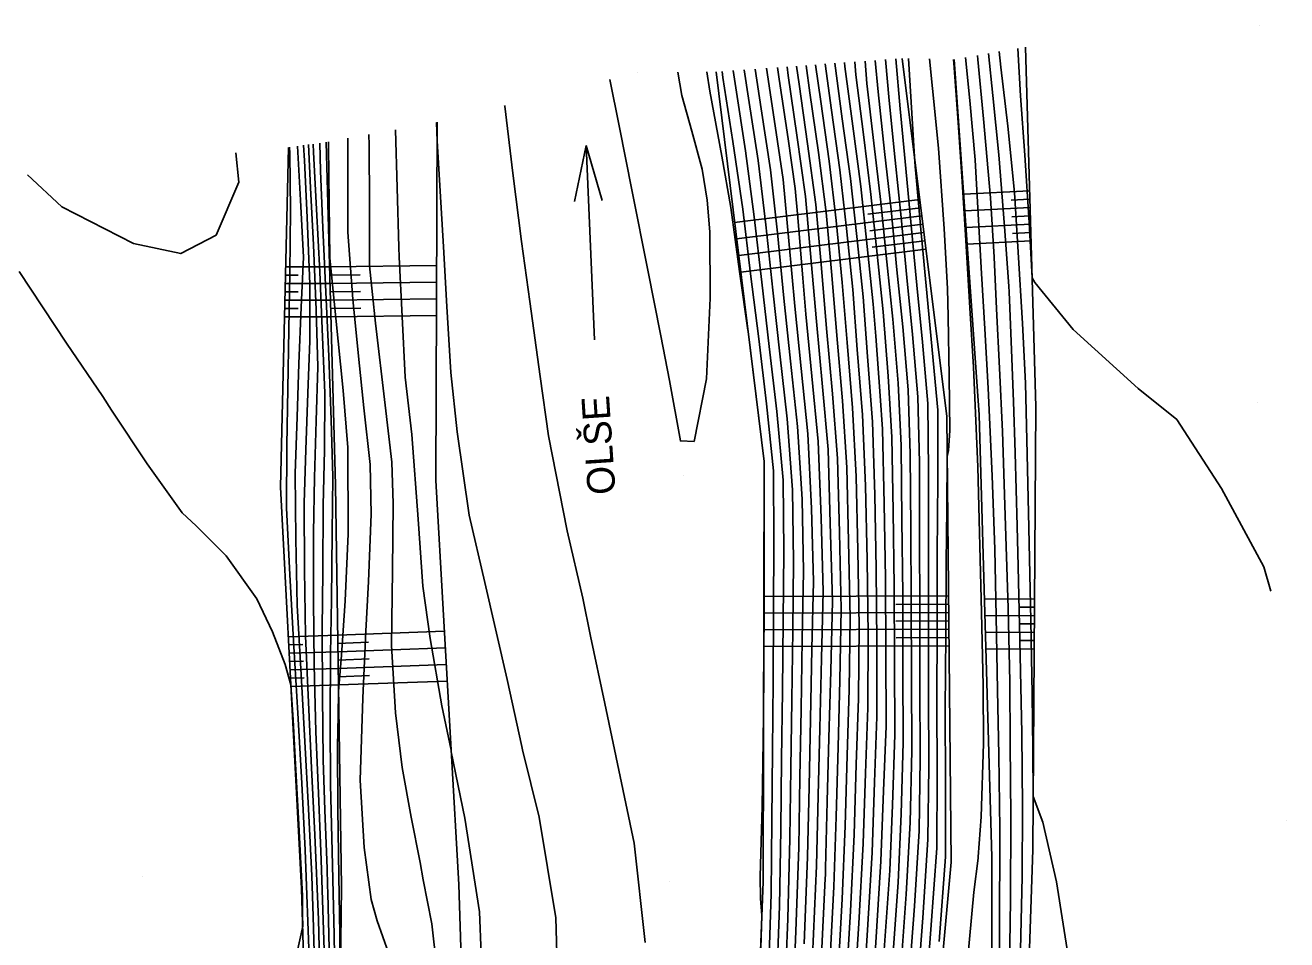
# Model space of a CAD drawing. Extents: x -448957 to -448612, y -1107690 to -1107245.
# Drawn here: x -448660.15 to -448614.67, y -1107277.56 to -1107244.62 of the extents above; entities that cross this region are included whole.
import ezdxf

# ---------------------------------------------------------------- set-up
doc = ezdxf.new("R2010")
doc.units = 0
for name, color, linetype in [('Default', 7, 'Continuous'), ('Vrstva 1', 7, 'Continuous'), ('Vrstva 14', 7, 'Continuous'), ('Vrstva 15', 7, 'Continuous'), ('Vrstva 16', 7, 'Continuous'), ('Vrstva 17', 7, 'Continuous'), ('Vrstva 45', 7, 'Continuous')]:
    doc.layers.add(name, color=color, linetype=linetype)

# ---------------------------------------------------------------- blocks, each defined once
blk = doc.blocks.new('POINT_DISPLAY')
at = {"layer": 'Default'}
blk.add_line((0, 0), (0, 0), dxfattribs=at)
blk = doc.blocks.new('TOK')
at = {"layer": 'Default'}
for p, q in [((-5, 50), (0, 70)), ((0, 0), (0, 70)), ((0, 70), (5, 50))]:
    blk.add_line(p, q, dxfattribs=at)

msp = doc.modelspace()

# ---------------------------------------------------------------- linework, layer by layer
at = {"layer": 'Vrstva 14'}
for p, q in [((-448623.72, -1107258.37), (-448624.094, -1107245.405)), ((-448626.923, -1107258.712), (-448628.535, -1107245.816)), ((-448625.755, -1107258.656), (-448626.659, -1107245.854)), ((-448633.514, -1107260.33), (-448635.246, -1107246.3)), ((-448645.345, -1107261.017), (-448645.297, -1107248.115)), ((-448650.94, -1107261.265), (-448650.655, -1107249.019)), ((-448648.961, -1107261.189), (-448649.302, -1107248.836)), ((-448626.769, -1107274.771), (-448626.923, -1107258.712)), ((-448625.299, -1107274.588), (-448625.755, -1107258.656)), ((-448623.821, -1107274.324), (-448623.72, -1107258.37)), ((-448633.55, -1107275.465), (-448633.514, -1107260.33)), ((-448644.514, -1107275.578), (-448645.345, -1107261.017)), ((-448650.184, -1107275.718), (-448650.94, -1107261.265)), ((-448648.744, -1107275.651), (-448648.961, -1107261.189)), ((-448625.345, -1107293.247), (-448625.299, -1107274.588)), ((-448624.486, -1107293.318), (-448623.821, -1107274.324)), ((-448628.426, -1107292.921), (-448626.769, -1107274.771)), ((-448643.962, -1107293.754), (-448644.514, -1107275.578)), ((-448634.19, -1107293.206), (-448633.55, -1107275.465)), ((-448649.646, -1107293.659), (-448650.184, -1107275.718)), ((-448648.982, -1107293.658), (-448648.744, -1107275.651))]:
    msp.add_line(p, q, dxfattribs=at)
at = {"layer": 'Vrstva 15'}
for p, q in [((-448623.944, -1107250.59), (-448626.316, -1107250.708)), ((-448627.9, -1107250.895), (-448634.576, -1107251.724)), ((-448623.936, -1107250.89), (-448624.613, -1107250.924)), ((-448627.826, -1107251.49), (-448634.503, -1107252.32)), ((-448627.863, -1107251.192), (-448629.77, -1107251.429)), ((-448623.927, -1107251.19), (-448626.274, -1107251.307)), ((-448623.918, -1107251.49), (-448624.589, -1107251.524)), ((-448627.789, -1107251.788), (-448629.696, -1107252.025)), ((-448623.91, -1107251.79), (-448626.232, -1107251.906)), ((-448627.751, -1107252.086), (-448634.429, -1107252.915)), ((-448627.714, -1107252.383), (-448629.622, -1107252.62)), ((-448623.893, -1107252.39), (-448626.189, -1107252.504)), ((-448623.901, -1107252.09), (-448624.565, -1107252.123)), ((-448627.677, -1107252.681), (-448634.356, -1107253.511)), ((-448650.755, -1107253.325), (-448649.178, -1107253.321)), ((-448649.178, -1107253.322), (-448645.316, -1107253.275)), ((-448650.762, -1107253.625), (-448650.303, -1107253.624)), ((-448649.17, -1107253.622), (-448648.072, -1107253.608)), ((-448650.776, -1107254.225), (-448650.308, -1107254.224)), ((-448650.769, -1107253.925), (-448649.162, -1107253.921)), ((-448649.162, -1107253.921), (-448645.318, -1107253.876)), ((-448649.153, -1107254.221), (-448648.061, -1107254.208)), ((-448650.783, -1107254.525), (-448649.145, -1107254.521)), ((-448649.145, -1107254.521), (-448645.321, -1107254.476)), ((-448650.797, -1107255.125), (-448649.129, -1107255.121)), ((-448650.79, -1107254.825), (-448650.313, -1107254.824)), ((-448649.137, -1107254.821), (-448648.049, -1107254.808)), ((-448649.129, -1107255.121), (-448645.323, -1107255.076)), ((-448626.861, -1107265.179), (-448633.526, -1107265.203)), ((-448626.858, -1107265.479), (-448628.762, -1107265.486)), ((-448623.764, -1107265.278), (-448625.565, -1107265.298)), ((-448623.766, -1107265.578), (-448624.28, -1107265.583)), ((-448626.855, -1107265.779), (-448633.527, -1107265.803)), ((-448623.768, -1107265.878), (-448625.548, -1107265.898)), ((-448648.88, -1107266.586), (-448645.035, -1107266.447)), ((-448626.849, -1107266.379), (-448633.528, -1107266.403)), ((-448626.852, -1107266.079), (-448628.759, -1107266.086)), ((-448623.771, -1107266.478), (-448625.531, -1107266.497)), ((-448623.769, -1107266.178), (-448624.278, -1107266.183)), ((-448650.659, -1107266.646), (-448648.88, -1107266.586)), ((-448650.643, -1107266.945), (-448650.141, -1107266.928)), ((-448648.876, -1107266.886), (-448647.77, -1107266.846)), ((-448626.847, -1107266.679), (-448628.755, -1107266.686)), ((-448623.773, -1107266.778), (-448624.276, -1107266.783)), ((-448650.627, -1107267.245), (-448648.871, -1107267.186)), ((-448648.871, -1107267.186), (-448645.001, -1107267.046)), ((-448626.844, -1107266.979), (-448633.53, -1107267.003)), ((-448623.775, -1107267.078), (-448625.513, -1107267.097)), ((-448650.612, -1107267.545), (-448650.116, -1107267.528)), ((-448650.596, -1107267.844), (-448648.862, -1107267.786)), ((-448648.867, -1107267.486), (-448647.754, -1107267.446)), ((-448648.862, -1107267.786), (-448644.967, -1107267.646)), ((-448650.58, -1107268.144), (-448650.091, -1107268.127)), ((-448648.858, -1107268.086), (-448647.737, -1107268.046)), ((-448648.853, -1107268.386), (-448644.933, -1107268.245)), ((-448650.565, -1107268.444), (-448648.853, -1107268.386))]:
    msp.add_line(p, q, dxfattribs=at)
at = {"layer": 'Vrstva 16'}
for points in [[(-448625.034, -1107245.57), (-448624.975, -1107246.128), (-448624.726, -1107248.256), (-448624.492, -1107250.651), (-448624.355, -1107252.799), (-448624.197, -1107255.366), (-448624.096, -1107257.514), (-448624.027, -1107260.071), (-448623.97, -1107262.72), (-448623.902, -1107266.064), (-448623.853, -1107268.714), (-448623.827, -1107270.707), (-448623.809, -1107272.4), (-448623.462, -1107273.321), (-448622.968, -1107275.478), (-448622.456, -1107278.756)], [(-448631.654, -1107246.041), (-448631.473, -1107247.37), (-448631.172, -1107249.517), (-448630.911, -1107251.655), (-448630.693, -1107253.887), (-448630.524, -1107256.046), (-448630.327, -1107258.407), (-448630.197, -1107260.88), (-448630.134, -1107263.547), (-448630.087, -1107266.27), (-448630.111, -1107268.878), (-448630.189, -1107271.246), (-448630.27, -1107273.776), (-448630.4, -1107276.535), (-448630.578, -1107279.549)], [(-448629.874, -1107245.913), (-448629.805, -1107246.717), (-448629.553, -1107248.868), (-448629.301, -1107250.993), (-448629.084, -1107253.146), (-448628.87, -1107255.214), (-448628.684, -1107257.512), (-448628.573, -1107259.76), (-448628.547, -1107262.436), (-448628.516, -1107265.124), (-448628.508, -1107267.805), (-448628.494, -1107270.456), (-448628.567, -1107273.023), (-448628.684, -1107275.497), (-448628.899, -1107278.516)], [(-448627.556, -1107245.836), (-448627.442, -1107246.899), (-448627.23, -1107249.047), (-448627.024, -1107251.959), (-448626.903, -1107254.106), (-448626.877, -1107255.121), (-448626.845, -1107257.262), (-448626.823, -1107259.214), (-448626.865, -1107259.937), (-448626.909, -1107260.153), (-448626.932, -1107262.019), (-448626.954, -1107263.985), (-448626.967, -1107266.578), (-448626.981, -1107269.265), (-448626.97, -1107271.909), (-448626.969, -1107274.577), (-448627.203, -1107277.623)], [(-448635.581, -1107246.303), (-448635.47, -1107246.998), (-448635.042, -1107249.34), (-448634.714, -1107251.183), (-448634.399, -1107253.491), (-448634.098, -1107255.602), (-448634.091, -1107255.654), (-448633.8, -1107257.991), (-448633.509, -1107260.335), (-448633.511, -1107262.858), (-448633.514, -1107265.387), (-448633.526, -1107267.587), (-448633.536, -1107269.774), (-448633.543, -1107270.068), (-448633.551, -1107270.392), (-448633.588, -1107272.762), (-448633.655, -1107275.283), (-448633.641, -1107276.077), (-448633.594, -1107276.689), (-448633.664, -1107279.033)], [(-448633.431, -1107246.169), (-448633.153, -1107248.002), (-448632.822, -1107250.173), (-448632.618, -1107252.385), (-448632.404, -1107254.742), (-448632.177, -1107256.989), (-448631.94, -1107259.339), (-448631.802, -1107262.03), (-448631.738, -1107264.663), (-448631.79, -1107267.087), (-448631.845, -1107269.614), (-448631.894, -1107272.044), (-448631.943, -1107274.571), (-448632.064, -1107277.71)], [(-448637.804, -1107277.666), (-448638.201, -1107274.086), (-448639.255, -1107269.048), (-448639.771, -1107266.623), (-448640.047, -1107265.257), (-448640.613, -1107262.833), (-448641.278, -1107259.412), (-448641.584, -1107257.268), (-448641.959, -1107254.568), (-448642.26, -1107252.415), (-448642.564, -1107249.955), (-448642.861, -1107247.54), (-448642.866, -1107247.512)], [(-448649.677, -1107279.715), (-448649.762, -1107276.72), (-448649.816, -1107275.256), (-448649.94, -1107272.847), (-448650.069, -1107270.417), (-448650.201, -1107268.008), (-448650.338, -1107265.528), (-448650.397, -1107263.118), (-448650.418, -1107260.77), (-448650.349, -1107258.729), (-448650.283, -1107256.819), (-448650.199, -1107254.777), (-448650.118, -1107252.977), (-448650.225, -1107250.927), (-448650.333, -1107248.975)], [(-448648.789, -1107279.043), (-448648.81, -1107277.349), (-448648.846, -1107275.273), (-448648.872, -1107272.862), (-448648.887, -1107270.593), (-448648.869, -1107269.486), (-448648.85, -1107268.62), (-448648.745, -1107267.309), (-448648.614, -1107265.354), (-448648.503, -1107262.937), (-448648.516, -1107259.826), (-448648.691, -1107257.773), (-448648.962, -1107255.055), (-448649.161, -1107253.003), (-448649.189, -1107251.032), (-448649.212, -1107248.966), (-448649.211, -1107248.82)]]:
    msp.add_lwpolyline(points, dxfattribs=at)
at = {"layer": 'Vrstva 17'}
for points in [[(-448624.366, -1107245.453), (-448624.268, -1107247.161), (-448624.118, -1107249.306), (-448623.959, -1107251.732), (-448623.854, -1107253.72), (-448623.759, -1107253.883), (-448622.375, -1107255.585), (-448620.025, -1107257.705), (-448618.636, -1107258.824), (-448617.028, -1107261.304), (-448615.497, -1107264.125), (-448615.243, -1107265.006)], [(-448631.311, -1107246.016), (-448631.084, -1107247.682), (-448630.786, -1107249.829), (-448630.542, -1107251.943), (-448630.319, -1107254.145), (-448630.156, -1107256.297), (-448629.966, -1107258.66), (-448629.861, -1107261.208), (-448629.803, -1107263.876), (-448629.766, -1107266.577), (-448629.777, -1107269.207), (-448629.86, -1107271.565), (-448629.946, -1107274.096), (-448630.1, -1107276.973), (-448630.287, -1107279.989)], [(-448630.968, -1107245.991), (-448630.695, -1107247.994), (-448630.4, -1107250.142), (-448630.172, -1107252.231), (-448629.946, -1107254.403), (-448629.787, -1107256.548), (-448629.605, -1107258.912), (-448629.524, -1107261.535), (-448629.471, -1107264.205), (-448629.444, -1107266.884), (-448629.444, -1107269.536), (-448629.532, -1107271.884), (-448629.623, -1107274.415), (-448629.8, -1107277.411), (-448629.995, -1107280.428)], [(-448630.613, -1107245.966), (-448630.601, -1107246.108), (-448630.316, -1107248.257), (-448630.027, -1107250.435), (-448629.8, -1107252.587), (-448629.579, -1107254.666), (-448629.491, -1107255.823), (-448629.334, -1107257.966), (-448629.244, -1107259.165), (-448629.188, -1107261.863), (-448629.14, -1107264.534), (-448629.123, -1107267.191), (-448629.111, -1107269.865), (-448629.203, -1107272.203), (-448629.3, -1107274.735), (-448629.501, -1107277.85)], [(-448630.243, -1107245.939), (-448630.203, -1107246.413), (-448629.934, -1107248.562), (-448629.664, -1107250.714), (-448629.442, -1107252.867), (-448629.224, -1107254.94), (-448629.043, -1107257.267), (-448628.903, -1107259.453), (-448628.865, -1107262.126), (-448628.825, -1107264.833), (-448628.813, -1107267.513), (-448628.799, -1107270.166), (-448628.886, -1107272.712), (-448628.981, -1107275.072), (-448629.191, -1107278.09)], [(-448629.505, -1107245.886), (-448629.407, -1107247.022), (-448629.172, -1107249.173), (-448628.937, -1107251.272), (-448628.726, -1107253.426), (-448628.516, -1107255.488), (-448628.325, -1107257.757), (-448628.243, -1107260.067), (-448628.228, -1107262.746), (-448628.206, -1107265.415), (-448628.203, -1107268.097), (-448628.189, -1107270.747), (-448628.247, -1107273.334), (-448628.388, -1107275.922), (-448628.608, -1107278.942)], [(-448629.135, -1107245.859), (-448629.01, -1107247.326), (-448628.791, -1107249.479), (-448628.574, -1107251.551), (-448628.368, -1107253.705), (-448628.161, -1107255.762), (-448627.966, -1107258.001), (-448627.913, -1107260.374), (-448627.909, -1107263.056), (-448627.896, -1107265.706), (-448627.897, -1107268.389), (-448627.884, -1107271.038), (-448627.927, -1107273.645), (-448628.092, -1107276.347), (-448628.317, -1107279.367)], [(-448628.766, -1107245.833), (-448628.612, -1107247.631), (-448628.409, -1107249.785), (-448628.21, -1107251.83), (-448628.01, -1107253.985), (-448627.807, -1107256.036), (-448627.607, -1107258.246), (-448627.583, -1107260.681), (-448627.591, -1107263.366), (-448627.586, -1107265.997), (-448627.592, -1107268.681), (-448627.58, -1107271.328), (-448627.608, -1107273.955), (-448627.796, -1107276.773), (-448628.025, -1107279.793)], [(-448628.31, -1107245.821), (-448628.092, -1107249.36), (-448628.062, -1107249.712), (-448628.028, -1107250.09), (-448627.847, -1107252.109), (-448627.652, -1107254.264), (-448627.452, -1107256.31), (-448627.248, -1107258.491), (-448627.253, -1107260.988), (-448627.272, -1107263.675), (-448627.277, -1107266.287), (-448627.286, -1107268.973), (-448627.275, -1107271.619), (-448627.288, -1107274.266), (-448627.499, -1107277.198), (-448627.734, -1107280.218)], [(-448626.691, -1107245.853), (-448626.678, -1107245.992), (-448626.52, -1107248.126), (-448626.369, -1107250.246), (-448626.237, -1107252.38), (-448626.092, -1107254.803), (-448625.968, -1107256.938), (-448625.813, -1107260.532), (-448625.676, -1107265.762), (-448625.621, -1107268.418), (-448625.604, -1107270.496), (-448625.692, -1107273.131), (-448625.792, -1107274.578), (-448625.796, -1107274.626), (-448625.949, -1107275.851), (-448626.195, -1107278.448)], [(-448626.25, -1107245.782), (-448626.098, -1107247.334), (-448625.905, -1107249.469), (-448625.796, -1107251.423), (-448625.68, -1107253.561), (-448625.562, -1107255.554), (-448625.435, -1107257.691), (-448625.291, -1107260.848), (-448625.196, -1107263.493), (-448625.149, -1107265.918), (-448625.094, -1107268.577), (-448625.057, -1107270.918), (-448625.016, -1107273.58), (-448625.026, -1107277.34), (-448625.065, -1107280.487)], [(-448625.824, -1107245.708), (-448625.81, -1107245.852), (-448625.603, -1107247.987), (-448625.349, -1107250.834), (-448625.225, -1107252.976), (-448625.138, -1107254.837), (-448625.029, -1107256.976), (-448624.922, -1107259.259), (-448624.835, -1107261.904), (-448624.721, -1107265.621), (-448624.658, -1107268.272), (-448624.638, -1107270.477), (-448624.617, -1107273.142), (-448624.631, -1107276.143), (-448624.681, -1107279.298)], [(-448625.428, -1107245.639), (-448625.268, -1107247.154), (-448625.048, -1107249.288), (-448624.849, -1107251.87), (-448624.697, -1107254.016), (-448624.682, -1107254.238), (-448624.671, -1107254.513), (-448624.599, -1107256.308), (-448624.521, -1107258.176), (-448624.461, -1107260.019), (-448624.389, -1107262.665), (-448624.354, -1107264.121), (-448624.291, -1107266.769), (-448624.223, -1107270.116), (-448624.204, -1107272.777), (-448624.216, -1107275.293), (-448624.279, -1107278.45)], [(-448636.619, -1107246.313), (-448636.473, -1107247.15), (-448636.112, -1107248.438), (-448635.751, -1107249.806), (-448635.566, -1107250.925), (-448635.469, -1107252.067), (-448635.457, -1107254.454), (-448635.594, -1107257.355), (-448636.039, -1107259.612), (-448636.528, -1107259.592), (-448636.926, -1107257.412), (-448637.236, -1107255.811), (-448637.708, -1107253.44), (-448638.269, -1107250.611), (-448638.738, -1107248.24), (-448639.07, -1107246.571)], [(-448635.03, -1107246.284), (-448634.997, -1107246.502), (-448634.637, -1107248.805), (-448634.282, -1107251.242), (-448633.998, -1107253.581), (-448633.708, -1107255.921), (-448633.428, -1107258.261), (-448633.168, -1107260.674), (-448633.157, -1107263.219), (-448633.169, -1107265.727), (-448633.191, -1107268.251), (-448633.211, -1107270.744), (-448633.228, -1107273.267), (-448633.259, -1107275.905), (-448633.357, -1107278.87)], [(-448634.63, -1107246.256), (-448634.536, -1107246.877), (-448634.184, -1107249.147), (-448633.866, -1107251.528), (-448633.599, -1107253.872), (-448633.326, -1107256.188), (-448633.056, -1107258.531), (-448632.826, -1107261.013), (-448632.802, -1107263.58), (-448632.825, -1107266.067), (-448632.854, -1107268.591), (-448632.881, -1107271.069), (-448632.906, -1107273.593), (-448632.96, -1107276.356), (-448633.068, -1107279.33)], [(-448634.231, -1107246.227), (-448634.075, -1107247.252), (-448633.73, -1107249.489), (-448633.45, -1107251.814), (-448633.201, -1107254.162), (-448632.943, -1107256.455), (-448632.684, -1107258.8), (-448632.485, -1107261.352), (-448632.447, -1107263.941), (-448632.48, -1107266.407), (-448632.518, -1107268.932), (-448632.552, -1107271.394), (-448632.585, -1107273.919), (-448632.662, -1107276.808), (-448632.779, -1107279.79)], [(-448633.831, -1107246.198), (-448633.614, -1107247.627), (-448633.276, -1107249.831), (-448633.034, -1107252.1), (-448632.803, -1107254.452), (-448632.56, -1107256.722), (-448632.312, -1107259.07), (-448632.143, -1107261.691), (-448632.093, -1107264.302), (-448632.135, -1107266.747), (-448632.181, -1107269.273), (-448632.223, -1107271.719), (-448632.264, -1107274.245), (-448632.363, -1107277.259), (-448632.49, -1107280.251)], [(-448633.032, -1107246.14), (-448632.967, -1107246.567), (-448632.649, -1107248.713), (-448632.388, -1107250.503), (-448632.297, -1107251.55), (-448632.117, -1107253.727), (-448632.006, -1107255.032), (-448631.795, -1107257.256), (-448631.568, -1107259.609), (-448631.461, -1107262.369), (-448631.383, -1107265.024), (-448631.445, -1107267.426), (-448631.508, -1107269.955), (-448631.565, -1107272.369), (-448631.621, -1107274.897), (-448631.766, -1107278.162)], [(-448632.685, -1107246.115), (-448632.642, -1107246.433), (-448632.329, -1107248.579), (-448632.019, -1107250.791), (-448631.812, -1107253.114), (-448631.629, -1107255.294), (-448631.411, -1107257.65), (-448631.207, -1107259.898), (-448631.129, -1107262.561), (-448631.051, -1107265.349), (-448631.11, -1107267.892), (-448631.175, -1107270.289), (-448631.234, -1107272.577), (-448631.294, -1107274.983), (-448631.3, -1107275.223), (-448631.307, -1107275.361), (-448631.458, -1107278.373)], [(-448632.341, -1107246.091), (-448632.252, -1107246.745), (-448631.943, -1107248.892), (-448631.649, -1107251.079), (-448631.439, -1107253.371), (-448631.261, -1107255.545), (-448631.05, -1107257.902), (-448630.871, -1107260.225), (-448630.797, -1107262.89), (-448630.729, -1107265.656), (-448630.777, -1107268.221), (-448630.846, -1107270.608), (-448630.916, -1107273.137), (-448631, -1107275.658), (-448631.16, -1107278.671)], [(-448631.998, -1107246.066), (-448631.863, -1107247.058), (-448631.557, -1107249.204), (-448631.28, -1107251.367), (-448631.066, -1107253.629), (-448630.892, -1107255.796), (-448630.688, -1107258.155), (-448630.534, -1107260.553), (-448630.466, -1107263.219), (-448630.408, -1107265.963), (-448630.444, -1107268.55), (-448630.517, -1107270.927), (-448630.593, -1107273.457), (-448630.7, -1107276.096), (-448630.869, -1107279.11)], [(-448640.941, -1107279.787), (-448641.017, -1107276.777), (-448641.625, -1107273.141), (-448642.22, -1107270.721), (-448642.246, -1107270.605), (-448642.777, -1107268.185), (-448643.58, -1107264.691), (-448644.141, -1107262.269), (-448644.582, -1107259.27), (-448644.808, -1107257.124), (-448644.953, -1107254.754), (-448645.066, -1107252.606), (-448645.193, -1107250.601), (-448645.3, -1107248.79), (-448645.321, -1107248.119)], [(-448647.049, -1107278.036), (-448647.464, -1107276.879), (-448647.671, -1107276.118), (-448647.93, -1107274.237), (-448648.07, -1107271.817), (-448647.979, -1107268.861), (-448647.871, -1107266.443), (-448647.778, -1107264.654), (-448647.677, -1107262.237), (-448647.713, -1107260.449), (-448647.94, -1107258.398), (-448648.134, -1107256.54), (-448648.341, -1107254.488), (-448648.512, -1107252.078), (-448648.517, -1107249.965), (-448648.512, -1107248.694)], [(-448645.147, -1107279.996), (-448645.491, -1107276.985), (-448645.806, -1107275.407), (-448645.915, -1107274.778), (-448646.239, -1107273.151), (-448646.553, -1107271.359), (-448646.797, -1107269.389), (-448646.938, -1107266.969), (-448646.906, -1107264.264), (-448646.877, -1107261.851), (-448646.932, -1107260.36), (-448647.176, -1107258.31), (-448647.523, -1107255.358), (-448647.731, -1107253.291), (-448647.741, -1107251.084), (-448647.745, -1107248.936), (-448647.756, -1107248.558)], [(-448643.651, -1107279.58), (-448643.773, -1107276.558), (-448644.297, -1107273.179), (-448644.787, -1107270.79), (-448644.791, -1107270.765), (-448644.796, -1107270.732), (-448645.127, -1107269.132), (-448645.554, -1107266.71), (-448645.818, -1107264.823), (-448645.986, -1107262.407), (-448646.21, -1107259.359), (-448646.446, -1107257.295), (-448646.556, -1107255.108), (-448646.663, -1107252.978), (-448646.676, -1107252.615), (-448646.736, -1107250.477), (-448646.797, -1107248.385)], [(-448660.066, -1107250.009), (-448658.823, -1107251.159), (-448656.243, -1107252.483), (-448654.539, -1107252.846), (-448653.258, -1107252.18), (-448652.446, -1107250.272), (-448652.55, -1107249.218)], [(-448649.894, -1107278.513), (-448650.05, -1107274.334), (-448650.175, -1107271.925), (-448650.318, -1107269.402), (-448650.458, -1107266.994), (-448650.61, -1107264.414), (-448650.723, -1107262.005), (-448650.715, -1107259.753), (-448650.675, -1107257.712), (-448650.64, -1107255.581), (-448650.605, -1107253.541), (-448650.589, -1107251.279), (-448650.606, -1107249.238), (-448650.618, -1107249.014)], [(-448649.5, -1107279.833), (-448649.579, -1107276.837), (-448649.706, -1107273.782), (-448649.823, -1107271.373), (-448649.94, -1107269.02), (-448650.045, -1107266.611), (-448650.075, -1107264.235), (-448650.094, -1107261.824), (-448650.036, -1107259.918), (-448649.962, -1107257.876), (-448649.892, -1107255.994), (-448649.881, -1107253.946), (-448649.985, -1107251.548), (-448650.081, -1107249.495), (-448650.11, -1107248.945)], [(-448649.359, -1107278.301), (-448649.475, -1107274.688), (-448649.579, -1107272.279), (-448649.674, -1107270.075), (-448649.732, -1107267.664), (-448649.758, -1107265.321), (-448649.75, -1107262.909), (-448649.719, -1107260.906), (-448649.654, -1107258.865), (-448649.593, -1107256.924), (-448649.658, -1107254.87), (-448649.754, -1107252.526), (-448649.858, -1107250.474), (-448649.939, -1107248.922)], [(-448649.168, -1107278.878), (-448649.235, -1107275.882), (-448649.244, -1107275.595), (-448649.267, -1107274.995), (-448649.346, -1107272.896), (-448649.407, -1107271.086), (-448649.43, -1107268.759), (-448649.445, -1107266.348), (-448649.423, -1107264.315), (-448649.401, -1107261.903), (-448649.354, -1107259.924), (-448649.345, -1107257.877), (-448649.438, -1107255.559), (-448649.525, -1107253.504), (-448649.642, -1107251.245), (-448649.752, -1107249.194), (-448649.767, -1107248.899)], [(-448648.965, -1107280.388), (-448649.015, -1107277.391), (-448649.085, -1107274.385), (-448649.139, -1107271.974), (-448649.158, -1107269.676), (-448649.142, -1107267.264), (-448649.108, -1107265.316), (-448649.083, -1107262.903), (-448649.054, -1107260.89), (-448649.113, -1107258.836), (-448649.203, -1107256.536), (-448649.295, -1107254.482), (-448649.422, -1107251.924), (-448649.5, -1107249.868), (-448649.522, -1107248.866)], [(-448650.619, -1107279.253), (-448650.143, -1107277.079), (-448650.146, -1107276.664), (-448650.156, -1107275.984), (-448650.284, -1107273.412), (-448650.41, -1107271.004), (-448650.492, -1107269.637), (-448650.568, -1107268.375), (-448650.778, -1107267.652), (-448651.237, -1107266.476), (-448651.797, -1107265.286), (-448652.901, -1107263.738), (-448653.978, -1107262.651), (-448654.484, -1107262.18), (-448655.749, -1107260.416), (-448657.032, -1107258.482), (-448657.352, -1107257.999), (-448658.661, -1107256.07), (-448660.363, -1107253.497)]]:
    msp.add_lwpolyline(points, dxfattribs=at)

# ---------------------------------------------------------------- block references
at = {"layer": 'Vrstva 1', "xscale": 0.1, "yscale": 0.10000000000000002}
for p in [(-448624.094, -1107245.405), (-448628.535, -1107245.816), (-448626.659, -1107245.854), (-448635.246, -1107246.3), (-448645.297, -1107248.115), (-448650.655, -1107249.019), (-448649.302, -1107248.836), (-448626.923, -1107258.712), (-448625.755, -1107258.656), (-448623.72, -1107258.37), (-448633.514, -1107260.33), (-448645.345, -1107261.017), (-448650.94, -1107261.265), (-448648.961, -1107261.189), (-448625.299, -1107274.588), (-448623.821, -1107274.324), (-448626.769, -1107274.771), (-448644.514, -1107275.578), (-448633.55, -1107275.465), (-448650.184, -1107275.718), (-448648.744, -1107275.651)]:
    msp.add_blockref('POINT_DISPLAY', p, dxfattribs=at)
at = {"layer": 'Vrstva 14', "xscale": 0.1, "yscale": 0.10000000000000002}
for p in [(-448615.66, -1107244.621), (-448638.081, -1107246.326), (-448615.712, -1107258.225), (-448636.427, -1107260.844), (-448614.673, -1107273.259), (-448655.926, -1107275.293), (-448636.906, -1107275.461)]:
    msp.add_blockref('POINT_DISPLAY', p, dxfattribs=at)
at = {"layer": 'Vrstva 45', "xscale": 0.1, "yscale": 0.09999999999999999, "rotation": 2.4745170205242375}
msp.add_blockref('TOK', (-448639.628, -1107255.948), dxfattribs=at)

# ---------------------------------------------------------------- texts
at = {"layer": 'Vrstva 45'}
msp.add_text('OLŠE', height=1, rotation=93.8372, dxfattribs=at).set_placement((-448638.865, -1107261.501))

doc.saveas('drawing.dxf')
